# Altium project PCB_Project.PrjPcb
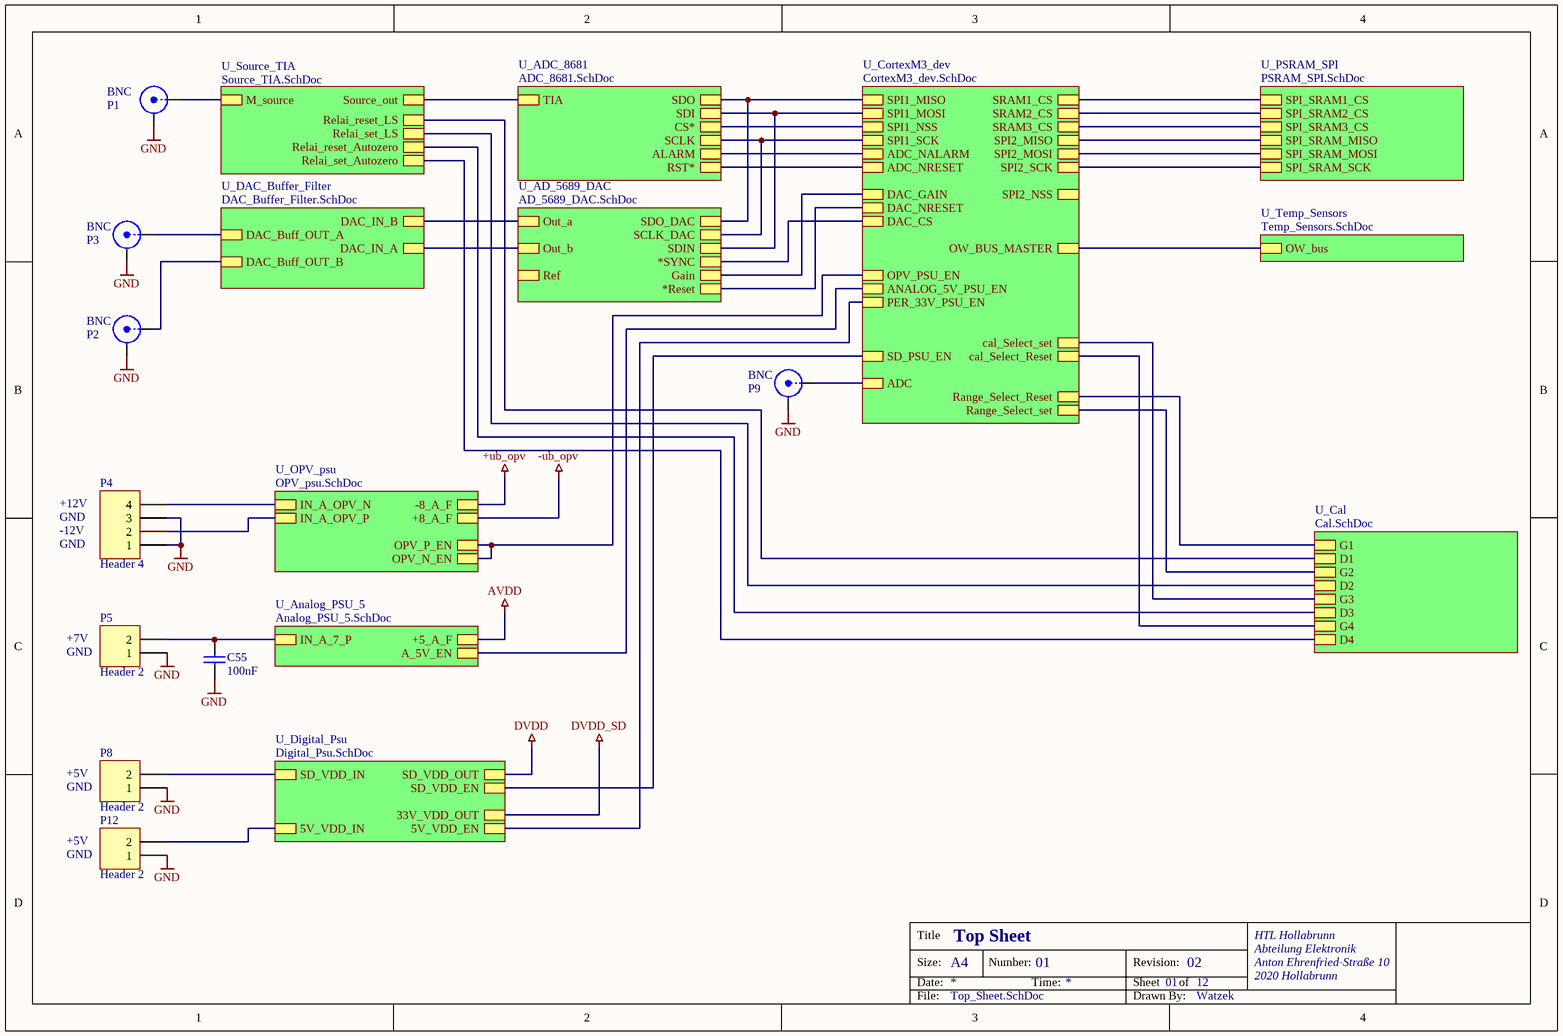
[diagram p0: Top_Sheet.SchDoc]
12 sheets, 142 parts. Net scope: hierarchical (ports join the sheet entries above them; power ports are global).
Board file: PCB1.PcbDoc
Sheets:
  Top_Sheet.SchDoc
    U_Source_TIA = Source_TIA.SchDoc
    U_PSRAM_SPI = PSRAM_SPI.SchDoc
    U_DAC_Buffer_Filter = DAC_Buffer_Filter.SchDoc
    U_ADC_8681 = ADC_8681.SchDoc
    U_AD_5689_DAC = AD_5689_DAC.SchDoc
    U_Temp_Sensors = Temp_Sensors.SchDoc
    U_Digital_Psu = Digital_Psu.SchDoc
    U_Analog_PSU_5 = Analog_PSU_5.SchDoc
    U_OPV_psu = OPV_psu.SchDoc
    U_CortexM3_dev = CortexM3_dev.SchDoc
    U_Cal = Cal.SchDoc

## Sheet Top_Sheet.SchDoc: Top Sheet
size A4; ApprovedBy: Watzek; CheckedBy: Watzek; Author: Watzek; DrawnBy: Watzek; Organization: HTL Hollabrunn; Address1: Abteilung Elektronik; Address2: Anton Ehrenfried-Straße 10; Address3: 2020 Hollabrunn; DocumentNumber: 01; Revision: 02; SheetNumber: 01; SheetTotal: 12; SPICEModelCacheIHPBHSPQ: <root> / <DocumentId>IHPBHSPQ</DocumentId> / <CacheFrame Number="0"> / <Model Name="cap" Kind="MDL"> / <Text>*Default semiconductor capacitor / .MODEL CAP C()</Text> / </Model> / </CacheFrame> / </root>

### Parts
C55  100nF  [C1206-KUE]
P1  BNC  [BNC_RA CON]
P2  BNC  [BNC_RA CON]
P3  BNC  [BNC_RA CON]
P4  Header 4  [HDR1X4]
P5  Header 2  [HDR1X2]
P8  Header 2  [HDR1X2]
P9  BNC  [BNC_RA CON]
P12  Header 2  [HDR1X2]

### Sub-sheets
U_AD_5689_DAC = AD_5689_DAC.SchDoc: Ref, Out_a, Out_b, SDIN, SDO_DAC, SCLK_DAC, *SYNC, Gain, *Reset
U_ADC_8681 = ADC_8681.SchDoc: SDI, CS*, SCLK, SDO, ALARM, RST*, TIA
U_Analog_PSU_5 = Analog_PSU_5.SchDoc: IN_A_7_P, +5_A_F, A_5V_EN
U_Cal = Cal.SchDoc: G1, G2, D1, D2, G3, D3, G4, D4
U_CortexM3_dev = CortexM3_dev.SchDoc: SPI1_NSS, SPI1_SCK, SPI1_MISO, SPI1_MOSI, SPI2_NSS, SPI2_MISO, SPI2_MOSI, SPI2_SCK, ADC_NALARM, ADC_NRESET, DAC_GAIN, DAC_NRESET, SRAM1_CS, SRAM2_CS, SRAM3_CS, DAC_CS, OW_BUS_MASTER, OPV_PSU_EN, ANALOG_5V_PSU_EN, PER_33V_PSU_EN, SD_PSU_EN, Range_Select_set, Range_Select_Reset, ADC, cal_Select_Reset, cal_Select_set
U_DAC_Buffer_Filter = DAC_Buffer_Filter.SchDoc: DAC_IN_B, DAC_Buff_OUT_B, DAC_IN_A, DAC_Buff_OUT_A
U_Digital_Psu = Digital_Psu.SchDoc: SD_VDD_IN, SD_VDD_OUT, SD_VDD_EN, 5V_VDD_IN, 33V_VDD_OUT, 5V_VDD_EN
U_OPV_psu = OPV_psu.SchDoc: IN_A_OPV_P, +8_A_F, IN_A_OPV_N, -8_A_F, OPV_P_EN, OPV_N_EN
U_PSRAM_SPI = PSRAM_SPI.SchDoc: SPI_SRAM_SCK, SPI_SRAM_MISO, SPI_SRAM1_CS, SPI_SRAM2_CS, SPI_SRAM3_CS, SPI_SRAM_MOSI
U_Source_TIA = Source_TIA.SchDoc: M_source, Source_out, Relai_set_LS, Relai_reset_LS, Relai_reset_Autozero, Relai_set_Autozero
U_Temp_Sensors = Temp_Sensors.SchDoc: OW_bus

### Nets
GND: C55.1 P1.2(Y) P2.2(Y) P3.2(Y) P4.1 P4.3 P5.1 P8.1 P9.2(Y) P12.1
M_source: P1.1(X) ; sheet U_Source_TIA/M_source
SPI1_CS_SRAM1: sheet U_PSRAM_SPI/SPI_SRAM1_CS, sheet U_CortexM3_dev/SRAM1_CS
SPI1_CS_SRAM2: sheet U_PSRAM_SPI/SPI_SRAM2_CS, sheet U_CortexM3_dev/SRAM2_CS
SPI1_CS_SRAM3: sheet U_PSRAM_SPI/SPI_SRAM3_CS, sheet U_CortexM3_dev/SRAM3_CS
SPI1_MISO: sheet U_ADC_8681/SDO, sheet U_AD_5689_DAC/SDO_DAC, sheet U_CortexM3_dev/SPI1_MISO
SPI1_MOSI: sheet U_ADC_8681/SDI, sheet U_AD_5689_DAC/SDIN, sheet U_CortexM3_dev/SPI1_MOSI
SPI1_SCK: sheet U_ADC_8681/SCLK, sheet U_AD_5689_DAC/SCLK_DAC, sheet U_CortexM3_dev/SPI1_SCK
SPI1_SRAM_MISO: sheet U_PSRAM_SPI/SPI_SRAM_MISO, sheet U_CortexM3_dev/SPI2_MISO
SPI1_SRAM_MOSI: sheet U_PSRAM_SPI/SPI_SRAM_MOSI, sheet U_CortexM3_dev/SPI2_MOSI
SPI1_SRAM_SCK: sheet U_PSRAM_SPI/SPI_SRAM_SCK, sheet U_CortexM3_dev/SPI2_SCK
NetC33_2: P8.2 ; sheet U_Digital_Psu/SD_VDD_IN
NetC36_2: P12.2 ; sheet U_Digital_Psu/5V_VDD_IN
NetC47_2: P4.2 ; sheet U_OPV_psu/IN_A_OPV_P
NetC49_2: P4.4 ; sheet U_OPV_psu/IN_A_OPV_N
NetC55_2: C55.2 P5.2 ; sheet U_Analog_PSU_5/IN_A_7_P
NetD5_2: sheet U_Source_TIA/Relai_set_LS, sheet U_Cal/D2
NetD6_2: sheet U_Source_TIA/Relai_reset_LS, sheet U_Cal/D1
NetD7_2: sheet U_Source_TIA/Relai_reset_Autozero, sheet U_Cal/D3
NetD8_2: sheet U_Source_TIA/Relai_set_Autozero, sheet U_Cal/D4
NetN3_7: sheet U_Source_TIA/Source_out, sheet U_ADC_8681/TIA
NetN3_11: sheet U_ADC_8681/CS*, sheet U_CortexM3_dev/SPI1_NSS
NetN3_14: sheet U_ADC_8681/ALARM, sheet U_CortexM3_dev/ADC_NALARM
NetN4_1: sheet U_AD_5689_DAC/*Reset, sheet U_CortexM3_dev/DAC_NRESET
NetN4_2: P9.1(X) ; sheet U_CortexM3_dev/ADC
NetN4_3: sheet U_AD_5689_DAC/*SYNC, sheet U_CortexM3_dev/DAC_CS
NetN4_4: sheet U_AD_5689_DAC/Gain, sheet U_CortexM3_dev/DAC_GAIN
NetN4_9: sheet U_CortexM3_dev/cal_Select_Reset, sheet U_Cal/G4
NetN4_10: sheet U_CortexM3_dev/cal_Select_set, sheet U_Cal/G3
NetN4_11: sheet U_CortexM3_dev/Range_Select_Reset, sheet U_Cal/G1
NetN4_12: sheet U_CortexM3_dev/Range_Select_set, sheet U_Cal/G2
NetN4_13: sheet U_OPV_psu/OPV_P_EN, sheet U_OPV_psu/OPV_N_EN, sheet U_CortexM3_dev/OPV_PSU_EN
NetN4_20: sheet U_Analog_PSU_5/A_5V_EN, sheet U_CortexM3_dev/ANALOG_5V_PSU_EN
NetN4_21: sheet U_Temp_Sensors/OW_bus, sheet U_CortexM3_dev/OW_BUS_MASTER
NetN4_27: sheet U_ADC_8681/RST*, sheet U_CortexM3_dev/ADC_NRESET
NetP2_1: P2.1(X) ; sheet U_DAC_Buffer_Filter/DAC_Buff_OUT_B
NetP3_1: P3.1(X) ; sheet U_DAC_Buffer_Filter/DAC_Buff_OUT_A
NetP7_10: sheet U_Digital_Psu/SD_VDD_EN, sheet U_CortexM3_dev/SD_PSU_EN
NetP7_12: sheet U_Digital_Psu/5V_VDD_EN, sheet U_CortexM3_dev/PER_33V_PSU_EN
NetR34_1: sheet U_DAC_Buffer_Filter/DAC_IN_B, sheet U_AD_5689_DAC/Out_a
NetR37_1: sheet U_DAC_Buffer_Filter/DAC_IN_A, sheet U_AD_5689_DAC/Out_b

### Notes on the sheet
- +12V
- GND
- -12V
- +7V
- +5V

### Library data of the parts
C55 = Capacitor: Manufacturer: Kemet; Bezeichnung: Kerko +-10% 63V
P1-P3 P9 = BNC: BNC Elbow Connector
P4 = Header 4: Header, 4-Pin
P5 P8 P12 = Header 2: Header, 2-Pin

## Sheet Source_TIA.SchDoc: TIA and damper
size A4; Author: Watzek; DrawnBy: Watzek; Organization: HTL Hollabrunn; Address1: Abteilung Elektronik; Address2: Anton Ehrenfried-Straße 10; Address3: 2020 Hollabrunn; DocumentNumber: 02; Revision: 02; SheetNumber: 02; SheetTotal: 12; SPICEModelCacheBSQSHVBX: <root> / <DocumentId>BSQSHVBX</DocumentId> / <CacheFrame Number="0"> / <Model Name="cap" Kind="MDL"> / <Text>*Default semiconductor capacitor / .MODEL CAP C()</Text> / </Model> / </CacheFrame> / </root>
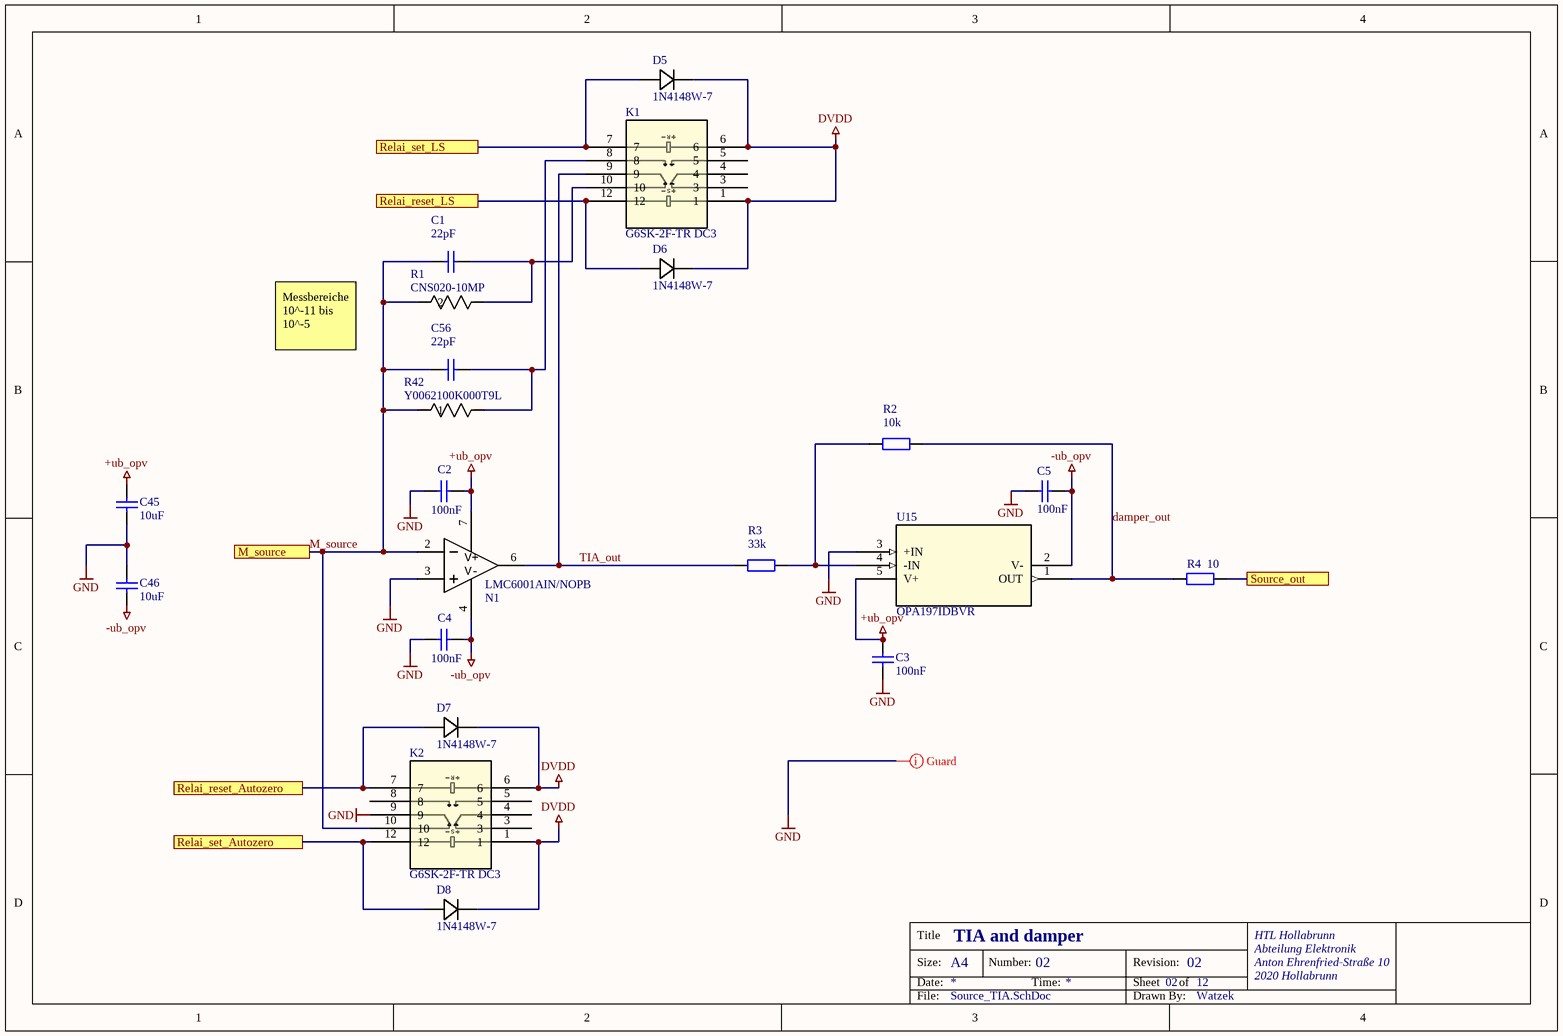
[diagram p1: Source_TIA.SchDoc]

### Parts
C1  22pF  [C1206-KUE]
C2  100nF  [C1206-KUE]
C3  100nF  [C1206-KUE]
C4  100nF  [C1206-KUE]
C5  100nF  [C1206-KUE]
C45  10uF  [C1206-KUE]
C46  10uF  [C1206-KUE]
C56  22pF  [C1206-KUE]
D5  1N4148W-7  [SOD123_DIO]
D6  1N4148W-7  [SOD123_DIO]
D7  1N4148W-7  [SOD123_DIO]
D8  1N4148W-7  [SOD123_DIO]
K1  G6SK-2F-TR DC3  [RELAY_G6SK-2F DC3_OMR]
K2  G6SK-2F-TR DC3  [RELAY_G6SK-2F DC3_OMR]
N1  LMC6001AIN/NOPB  [DIP8]
R1  CNS020-10MP  [RES_CNS020_VIS]
R2  10k  [C1206-KUE]
R3  33k  [C1206-KUE]
R4  10  [C1206-KUE]
R42  Y0062100K000T9L  [RES_S102K_7P62X2P67_VIS]
U15  OPA197IDBVR  [DBV5_TEX]

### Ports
M_source, Relai_reset_Autozero, Relai_reset_LS, Relai_set_Autozero, Relai_set_LS, Source_out

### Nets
+ub_opv: C2.2 C3.2 C45.2 N1.7(V+) U15.5(V+)  [project net neg_out]
-ub_opv: C4.2 C5.2 C46.1 N1.4(V-) U15.2(V-)  [project net pos_out]
DVDD: D5.1 D6.1 D7.1 D8.1 K1.1 K1.6 K2.1 K2.6
GND: C2.1 C3.1 C4.1 C5.1 C45.1 C46.2 K2.9 N1.3(IN+) U15.3(+IN)
damper_out: R2.1 R4.2 U15.1(OUT)
M_source: C1.1 C56.1 K2.10 N1.2(IN-) R1.2 R42.1 ; port M_source
TIA_out: K1.9 N1.6(OUT) R3.2
NetC1_2: C1.2 K1.10 R1.1
NetC56_2: C56.2 K1.8 R42.2
NetD5_2: D5.2 K1.7 ; port Relai_set_LS
NetD6_2: D6.2 K1.12 ; port Relai_reset_LS
NetD7_2: D7.2 K2.7 ; port Relai_reset_Autozero
NetD8_2: D8.2 K2.12 ; port Relai_set_Autozero
NetN3_7: R4.1 ; port Source_out
NetR2_2: R2.2 R3.1 U15.4(-IN)

Not connected (* = marked no-connect by the designer): K1 3 4 5; K2 3 4 5 8

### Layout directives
mark named Guard: GND

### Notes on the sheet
- Messbereiche 10^-11 bis 10^-5

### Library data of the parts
C1-C5 C45 C46 C56 = Capacitor: as C55 on sheet Top_Sheet
D5-D8 = 1N4148W-7: Description; Manufacturer_Name: Diodes Inc
K1 K2 = G6SK-2F-TR DC3: Description; Manufacturer_Name: Omron
N1 = LMC6001AINNOPB: Ultra-Low Input Current Amplifier 8-PDIP -40 to 85; Manufacturer_Name: Texas Instruments; Manufacturer: NationalSemiconductor; Characteristics: LMC6001AINUltra-LowInputBiasCurrentOpAmp; CompType: OpAmpIC; TaMin_C: -400; TaMax_C: 850; ComponentLink1DescBC: LMC6001Datasheet; ComponentLink2DescA4: LMC6001WebPage; ComponentLink3DescAC: N08EPackageWebPage
R1 = CNS020-10KP: CNS 020 10K 0,02% e2; Manufacturer_Name: Vishay
R2-R4 = ResistorSMD: Resistor SMD; Manufacturer: AVX; Bezeichnung: SMD Wid. 1/8W 2%
R42 = Y0062100K000T9L: No Description Available; Manufacturer_Name: Vishay
U15 = OPA197IDBVR: Single, 36-V, precision, rail-to-rail input output, low offset voltage op amp 5-SOT-23 -40 to 125; Manufacturer_Name: Texas Instruments

## Sheet PSRAM_SPI.SchDoc: SRAM
size A4; DrawnBy: Michael Watzek; Organization: HTL Hollabrunn; Address1: Abteilung Elektronik; Address2: Anton Ehrenfried-Straße 10; Address3: 2020 Hollabrunn; DocumentNumber: 08; Revision: 02; SheetNumber: 08; SheetTotal: 12; SPICEModelCacheKLVIFSCJ: <root> / <DocumentId>KLVIFSCJ</DocumentId> / <CacheFrame Number="0"> / <Model Name="cap" Kind="MDL"> / <Text>*Default semiconductor capacitor / .MODEL CAP C()</Text> / </Model> / </CacheFrame> / </root>
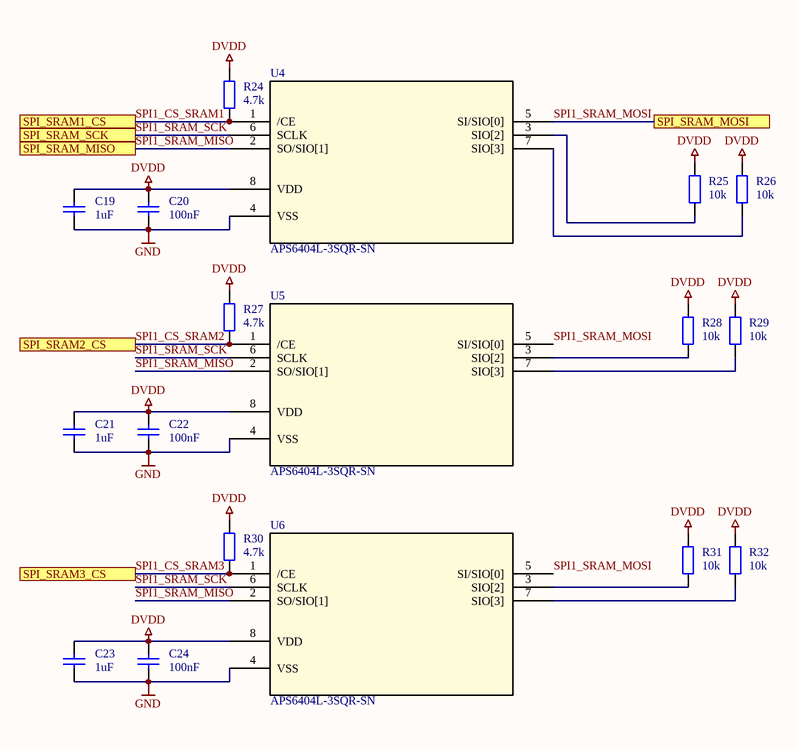
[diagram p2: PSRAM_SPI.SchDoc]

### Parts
C19  1uF  [C1206-KUE]
C20  100nF  [C1206-KUE]
C21  1uF  [C1206-KUE]
C22  100nF  [C1206-KUE]
C23  1uF  [C1206-KUE]
C24  100nF  [C1206-KUE]
R24  4.7k  [C1206-KUE]
R25  10k  [C1206-KUE]
R26  10k  [C1206-KUE]
R27  4.7k  [C1206-KUE]
R28  10k  [C1206-KUE]
R29  10k  [C1206-KUE]
R30  4.7k  [C1206-KUE]
R31  10k  [C1206-KUE]
R32  10k  [C1206-KUE]
U4  APS6404L-3SQR-SN  [APS6404L-3SQR-SN_APY]
U5  APS6404L-3SQR-SN  [APS6404L-3SQR-SN_APY]
U6  APS6404L-3SQR-SN  [APS6404L-3SQR-SN_APY]

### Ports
SPI_SRAM1_CS, SPI_SRAM2_CS, SPI_SRAM3_CS, SPI_SRAM_MISO, SPI_SRAM_MOSI, SPI_SRAM_SCK

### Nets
DVDD: C19.2 C20.2 C21.2 C22.2 C23.2 C24.2 R24.1 R25.1 R26.1 R27.1 R28.1 R29.1 R30.1 R31.1 R32.1 U4.8(VDD) U5.8(VDD) U6.8(VDD)
GND: C19.1 C20.1 C21.1 C22.1 C23.1 C24.1 U4.4(VSS) U5.4(VSS) U6.4(VSS)
SPI1_CS_SRAM1: R24.2 U4.1(/CE) ; port SPI_SRAM1_CS
SPI1_CS_SRAM2: R27.2 U5.1(/CE) ; port SPI_SRAM2_CS
SPI1_CS_SRAM3: R30.2 U6.1(/CE) ; port SPI_SRAM3_CS
SPI1_SRAM_MISO: U4.2(SO/SIO[1]) U5.2(SO/SIO[1]) U6.2(SO/SIO[1]) ; port SPI_SRAM_MISO
SPI1_SRAM_MOSI: U4.5(SI/SIO[0]) U5.5(SI/SIO[0]) U6.5(SI/SIO[0]) ; port SPI_SRAM_MOSI
SPI1_SRAM_SCK: U4.6(SCLK) U5.6(SCLK) U6.6(SCLK) ; port SPI_SRAM_SCK
NetR25_2: R25.2 U4.3(SIO[2])
NetR26_2: R26.2 U4.7(SIO[3])
NetR28_2: R28.2 U5.3(SIO[2])
NetR29_2: R29.2 U5.7(SIO[3])
NetR31_2: R31.2 U6.3(SIO[2])
NetR32_2: R32.2 U6.7(SIO[3])

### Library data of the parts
C19-C24 = Capacitor: as C55 on sheet Top_Sheet
R24-R32 = ResistorSMD: as R2 on sheet Source_TIA
U4-U6 = APS6404L-3SQR-SN: Description; Manufacturer_Name: AP Memory

## Sheet DAC_Buffer_Filter.SchDoc: DAC Buffer
size A4; DrawnBy: Michael Watzek; Organization: HTL Hollabrunn; Address1: Abteilung Elektronik; Address2: Anton Ehrenfried-Straße 10; Address3: 2020 Hollabrunn; DocumentNumber: 09; Revision: 01; SheetNumber: 09; SheetTotal: 12; SPICEModelCacheDRLOHMHD: <root> / <DocumentId>DRLOHMHD</DocumentId> / <CacheFrame Number="0"> / <Model Name="cap" Kind="MDL"> / <Text>*Default semiconductor capacitor / .MODEL CAP C()</Text> / </Model> / </CacheFrame> / </root>
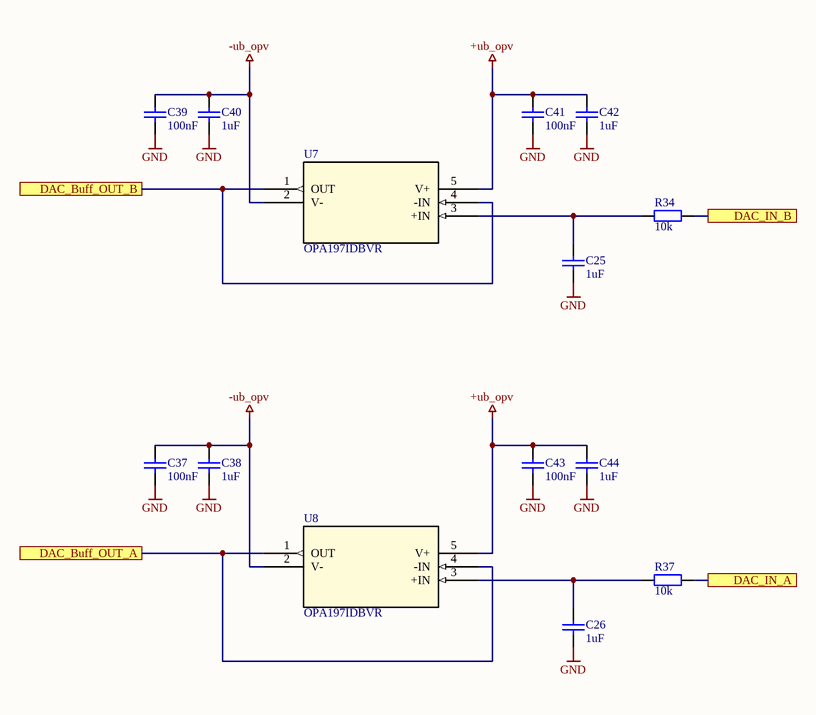
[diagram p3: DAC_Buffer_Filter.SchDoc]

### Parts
C25  1uF  [C1206-KUE]
C26  1uF  [C1206-KUE]
C37  100nF  [C1206-KUE]
C38  1uF  [C1206-KUE]
C39  100nF  [C1206-KUE]
C40  1uF  [C1206-KUE]
C41  100nF  [C1206-KUE]
C42  1uF  [C1206-KUE]
C43  100nF  [C1206-KUE]
C44  1uF  [C1206-KUE]
R34  10k  [C1206-KUE]
R37  10k  [C1206-KUE]
U7  OPA197IDBVR  [DBV5_TEX]
U8  OPA197IDBVR  [DBV5_TEX]

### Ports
DAC_Buff_OUT_A, DAC_Buff_OUT_B, DAC_IN_A, DAC_IN_B

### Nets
+ub_opv: C41.2 C42.2 C43.2 C44.2 U7.5(V+) U8.5(V+)  [project net neg_out]
-ub_opv: C37.2 C38.2 C39.2 C40.2 U7.2(V-) U8.2(V-)  [project net pos_out]
GND: C25.1 C26.1 C37.1 C38.1 C39.1 C40.1 C41.1 C42.1 C43.1 C44.1
NetC25_2: C25.2 R34.2 U7.3(+IN)
NetC26_2: C26.2 R37.2 U8.3(+IN)
NetP2_1: U7.1(OUT) U7.4(-IN) ; port DAC_Buff_OUT_B
NetP3_1: U8.1(OUT) U8.4(-IN) ; port DAC_Buff_OUT_A
NetR34_1: R34.1 ; port DAC_IN_B
NetR37_1: R37.1 ; port DAC_IN_A

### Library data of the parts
C25 C26 C37-C44 = Capacitor: as C55 on sheet Top_Sheet
R34 R37 = ResistorSMD: as R2 on sheet Source_TIA
U7 U8 = OPA197IDBVR: as U15 on sheet Source_TIA

## Sheet ADC_8681.SchDoc: source ADC
size A4; Author: Watzek; DrawnBy: Watzek; Organization: HTL Hollabrunn; Address1: Abteilung Elektronik; Address2: Anton Ehrenfried-Straße 10; Address3: 2020 Hollabrunn; DocumentNumber: 04; Revision: 01; SheetNumber: 04; SheetTotal: 12; SPICEModelCacheSWPEVHXS: <root> / <DocumentId>SWPEVHXS</DocumentId> / <CacheFrame Number="0"> / <Model Name="cap" Kind="MDL"> / <Text>*Default semiconductor capacitor / .MODEL CAP C()</Text> / </Model> / </CacheFrame> / </root>
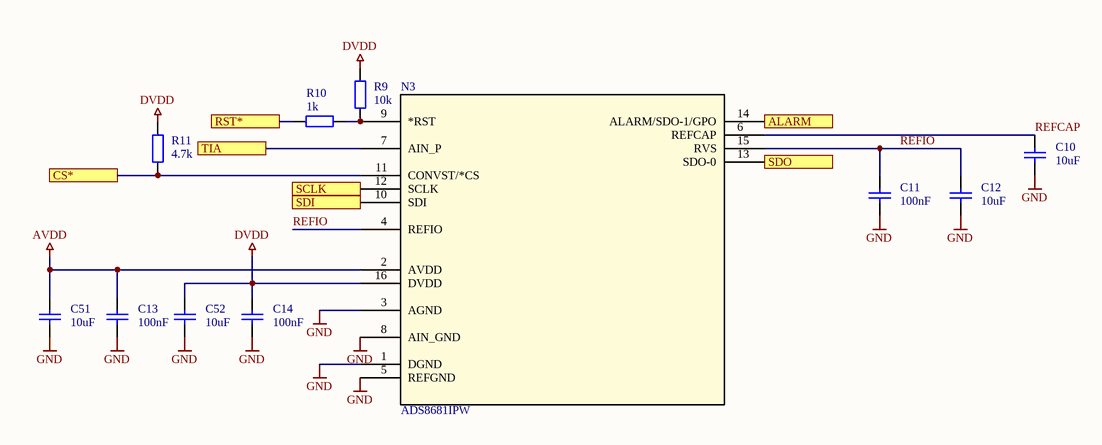
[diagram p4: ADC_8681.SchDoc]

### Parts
C10  10uF  [C1206-KUE]
C11  100nF  [C1206-KUE]
C12  10uF  [C1206-KUE]
C13  100nF  [C1206-KUE]
C14  100nF  [C1206-KUE]
C51  10uF  [C1206-KUE]
C52  10uF  [C1206-KUE]
N3  ADS8681IPW  [PW16_TEX]
R9  10k  [C1206-KUE]
R10  1k  [C1206-KUE]
R11  4.7k  [C1206-KUE]

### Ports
ALARM, CS*, RST*, SCLK, SDI, SDO, TIA

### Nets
AVDD: C13.2 C51.2 N3.2(AVDD)
DVDD: C14.2 C52.2 N3.16(DVDD) R9.1 R11.1
GND: C10.1 C11.1 C12.1 C13.1 C14.1 C51.1 C52.1 N3.1(DGND) N3.3(AGND) N3.5(REFGND) N3.8(AIN_GND)
REFCAP: C10.2 N3.6(REFCAP)
REFIO: C11.2 C12.2 N3.4(REFIO) N3.15(RVS)
SPI1_MISO: N3.13(SDO-0) ; port SDO
SPI1_MOSI: N3.10(SDI) ; port SDI
SPI1_SCK: N3.12(SCLK) ; port SCLK
NetN3_7: N3.7(AIN_P) ; port TIA
NetN3_9: N3.9(*RST) R9.2 R10.2
NetN3_11: N3.11(CONVST/*CS) R11.2 ; port CS*
NetN3_14: N3.14(ALARM/SDO-1/GPO) ; port ALARM
NetN4_27: R10.1 ; port RST*

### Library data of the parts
C10-C14 C51 C52 = Capacitor: as C55 on sheet Top_Sheet
N3 = ADS8681IPW: 16-bit, 1MSPS 1-ch SAR ADC with programmable (Â±12V, Â±10V, Â±6V, Â±5V, Â±2.5V) input ranges on 5V supply 16-TSSOP -40 to 125; Manufacturer_Name: Texas Instruments
R9-R11 = ResistorSMD: as R2 on sheet Source_TIA

## Sheet AD_5689_DAC.SchDoc: DAC for Gate / Drain
size A4; Author: Watzek; DrawnBy: Watzek; Organization: HTL Hollabrunn; Address1: Abteilung Elektronik; Address2: Anton Ehrenfried-Straße 10; Address3: 2020 Hollabrunn; DocumentNumber: 05; Revision: 01; SheetNumber: 05; SheetTotal: 12; SPICEModelCacheXXRROZRR: <root> / <DocumentId>XXRROZRR</DocumentId> / <CacheFrame Number="0"> / <Model Name="cap" Kind="MDL"> / <Text>*Default semiconductor capacitor / .MODEL CAP C()</Text> / </Model> / </CacheFrame> / </root>
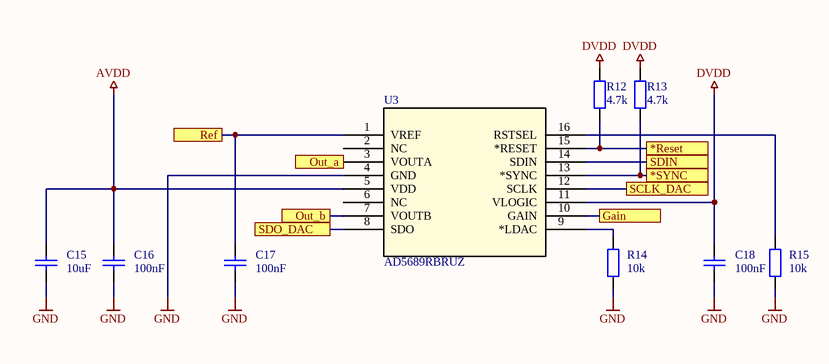
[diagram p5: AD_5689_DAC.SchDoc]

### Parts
C15  10uF  [C1206-KUE]
C16  100nF  [C1206-KUE]
C17  100nF  [C1206-KUE]
C18  100nF  [C1206-KUE]
R12  4.7k  [C1206-KUE]
R13  4.7k  [C1206-KUE]
R14  10k  [C1206-KUE]
R15  10k  [C1206-KUE]
U3  AD5689RBRUZ  [RU_16_ADI]

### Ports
*Reset, *SYNC, Gain, Out_a, Out_b, Ref, SCLK_DAC, SDIN, SDO_DAC

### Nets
AVDD: C15.2 C16.2 U3.5(VDD)
DVDD: C18.2 R12.1 R13.1 U3.11(VLOGIC)
GND: C15.1 C16.1 C17.1 C18.1 R14.2 R15.2 U3.4(GND)
SPI1_MISO: U3.8(SDO) ; port SDO_DAC
SPI1_MOSI: U3.14(SDIN) ; port SDIN
SPI1_SCK: U3.12(SCLK) ; port SCLK_DAC
NetC17_2: C17.2 U3.1(VREF) ; port Ref
NetN4_1: R12.2 U3.15(*RESET) ; port *Reset
NetN4_3: R13.2 U3.13(*SYNC) ; port *SYNC
NetN4_4: U3.10(GAIN) ; port Gain
NetR14_1: R14.1 U3.9(*LDAC)
NetR15_1: R15.1 U3.16(RSTSEL)
NetR34_1: U3.3(VOUTA) ; port Out_a
NetR37_1: U3.7(VOUTB) ; port Out_b

Not connected (* = marked no-connect by the designer): U3 2(NC) 6(NC)

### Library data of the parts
C15-C18 = Capacitor: as C55 on sheet Top_Sheet
R12-R15 = ResistorSMD: as R2 on sheet Source_TIA
U3 = AD5689RBRUZ: Dual, 16-Bit nanoDAC+ with 2 ppm/Â°C Reference, SPI Interface; Manufacturer_Name: Analog Devices Inc

## Sheet Temp_Sensors.SchDoc: One Wire Devices
size A4; DrawnBy: Michael Watzek; Organization: HTL Hollabrunn; Address1: Abteilung Elektronik; Address2: Anton Ehrenfried-Straße 10; Address3: 2020 Hollabrunn; DocumentNumber: 10; Revision: 01; SheetNumber: 10; SheetTotal: 12
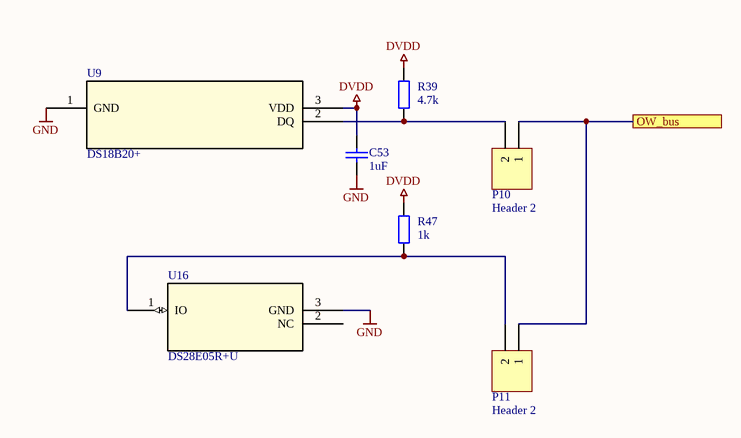
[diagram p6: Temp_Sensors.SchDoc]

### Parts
C53  1uF  [C1206-KUE]
P10  Header 2  [HDR1X2]
P11  Header 2  [HDR1X2]
R39  4.7k  [C1206-KUE]
R47  1k  [C1206-KUE]
U9  DS18B20+  [21-0248A_Q3-1_MXM]
U16  DS28E05R+U  [21-0051H_MXM]

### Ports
OW_bus

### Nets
DVDD: C53.2 R39.1 R47.1 U9.3(VDD)
GND: C53.1 U9.1(GND) U16.3(GND)
NetN4_21: P10.1 P11.1 ; port OW_bus
NetP10_2: P10.2 R39.2 U9.2(DQ)
NetP11_2: P11.2 R47.2 U16.1(IO)

Not connected (* = marked no-connect by the designer): U16 2(NC)

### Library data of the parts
C53 = Capacitor: as C55 on sheet Top_Sheet
P10 P11 = Header 2: Header, 2-Pin
R39 R47 = ResistorSMD: as R2 on sheet Source_TIA
U9 = DS18B20+: Programmable Resolution 1-Wire Digital Thermometer; Manufacturer_Name: Analog Devices Inc
U16 = DS28E05R+U: 1-Wire EEPROM; Manufacturer_Name: Analog Devices Inc

## Sheet Digital_Psu.SchDoc: Digital PSU
size A4; DrawnBy: Michael Watzek; Organization: HTL Hollabrunn; Address1: Abteilung Elektronik; Address2: Anton Ehrenfried-Straße 10; Address3: 2020 Hollabrunn; DocumentNumber: 07; Revision: 02; SheetNumber: 07; SheetTotal: 12; SPICEModelCacheAWIPVUZH: <root> / <DocumentId>AWIPVUZH</DocumentId> / <CacheFrame Number="0"> / <Model Name="cap" Kind="MDL"> / <Text>*Default semiconductor capacitor / .MODEL CAP C()</Text> / </Model> / </CacheFrame> / </root>
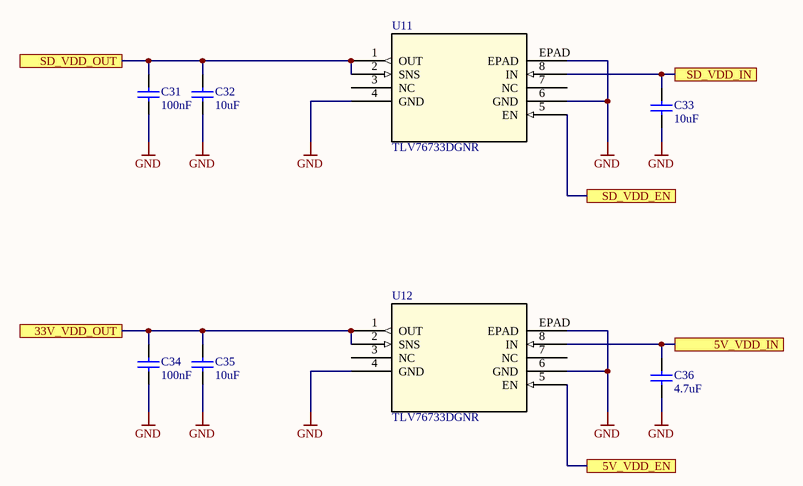
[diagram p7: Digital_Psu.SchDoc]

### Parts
C31  100nF  [C1206-KUE]
C32  10uF  [C1206-KUE]
C33  10uF  [C1206-KUE]
C34  100nF  [C1206-KUE]
C35  10uF  [C1206-KUE]
C36  4.7uF  [C1206-KUE]
U11  TLV76733DGNR  [VSSOP8_DGN_TEX]
U12  TLV76733DGNR  [VSSOP8_DGN_TEX]

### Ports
5V_VDD_EN, 5V_VDD_IN, 33V_VDD_OUT, SD_VDD_EN, SD_VDD_IN, SD_VDD_OUT

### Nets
DVDD: C31.2 C32.2 U11.1(OUT) U11.2(SNS) ; port SD_VDD_OUT
DVDD_SD: C34.2 C35.2 U12.1(OUT) U12.2(SNS) ; port 33V_VDD_OUT
GND: C31.1 C32.1 C33.1 C34.1 C35.1 C36.1 U11.4(GND) U11.6(GND) U11.EPAD U12.4(GND) U12.6(GND) U12.EPAD
NetC33_2: C33.2 U11.8(IN) ; port SD_VDD_IN
NetC36_2: C36.2 U12.8(IN) ; port 5V_VDD_IN
NetP7_10: U11.5(EN) ; port SD_VDD_EN
NetP7_12: U12.5(EN) ; port 5V_VDD_EN

Not connected (* = marked no-connect by the designer): U11 3(NC) 7(NC); U12 3(NC) 7(NC)

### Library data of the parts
C31-C36 = Capacitor: as C55 on sheet Top_Sheet
U11 U12 = TLV76733DGNR: Adjustable- and fixed-output, 1-A, 16-V, positive-voltage low-dropout (LDO) linear regulator 8-HVSSOP -40 to 125; Manufacturer_Name: Texas Instruments

## Sheet Analog_PSU_5.SchDoc: Analog PSU
size A4; DrawnBy: Michael Watzek; Organization: HTL Hollabrunn; Address1: Abteilung Elektronik; Address2: Anton Ehrenfried-Straße 10; Address3: 2020 Hollabrunn; DocumentNumber: 11; Revision: 02; SheetNumber: 11; SheetTotal: 12; SPICEModelCacheRYPOANGS: <root> / <DocumentId>RYPOANGS</DocumentId> / <CacheFrame Number="0"> / <Model Name="cap" Kind="MDL"> / <Text>*Default semiconductor capacitor / .MODEL CAP C()</Text> / </Model> / </CacheFrame> / </root>
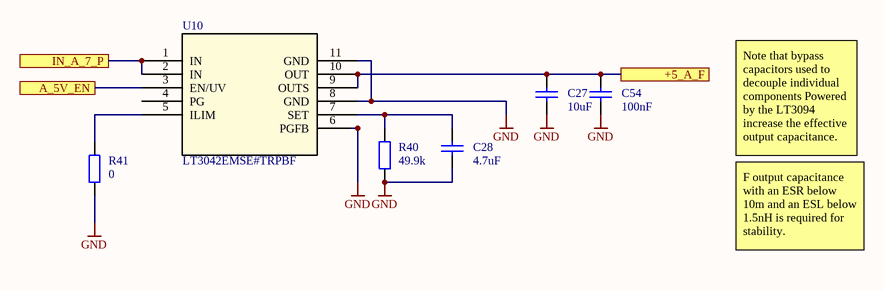
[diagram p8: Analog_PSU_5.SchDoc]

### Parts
C27  10uF  [C1206-KUE]
C28  4.7uF  [C1206-KUE]
C54  100nF  [C1206-KUE]
R40  49.9k  [C1206-KUE]
R41  0  [C1206-KUE]
U10  LT3042EMSE#TRPBF  [05-08-1664_ADI]

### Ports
+5_A_F, A_5V_EN, IN_A_7_P

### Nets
AVDD: C27.2 C54.2 U10.9(OUTS) U10.10(OUT) ; port +5_A_F
GND: C27.1 C28.1 C54.1 R40.2 R41.2 U10.6(PGFB) U10.8(GND) U10.11(GND)
NetC28_2: C28.2 R40.1 U10.7(SET)
NetC55_2: U10.1(IN) U10.2(IN) ; port IN_A_7_P
NetN4_20: U10.3(EN/UV) ; port A_5V_EN
NetR41_1: R41.1 U10.5(ILIM)

Not connected (* = marked no-connect by the designer): U10 4(PG)

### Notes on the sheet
- Note that bypass capacitors used to decouple individual components Powered by the LT3094 increase the effective output capacitance.
- F output capacitance with an ESR below 10m and an ESL below 1.5nH is required for stability.

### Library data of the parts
C27 C28 C54 = Capacitor: as C55 on sheet Top_Sheet
R40 R41 = ResistorSMD: as R2 on sheet Source_TIA
U10 = LT3042EMSETRPBF: 20V, 200mA, Ultralow Noise, Ultrahigh PSRR RF Linear Regulator; Manufacturer_Name: Analog Devices Inc

## Sheet OPV_psu.SchDoc: OPV Power supply
size A4; DrawnBy: Watzek; Organization: HTL Hollabrunn; Address1: Abteilung Elektronik; Address2: Anton Ehrenfried-Straße 10; Address3: 2020 Hollabrunn; DocumentNumber: 03; Revision: 01; SheetNumber: 03; SheetTotal: 12; SPICEModelCacheVBIYTPZR: <root> / <DocumentId>VBIYTPZR</DocumentId> / <CacheFrame Number="0"> / <Model Name="cap" Kind="MDL"> / <Text>*Default semiconductor capacitor / .MODEL CAP C()</Text> / </Model> / </CacheFrame> / </root>
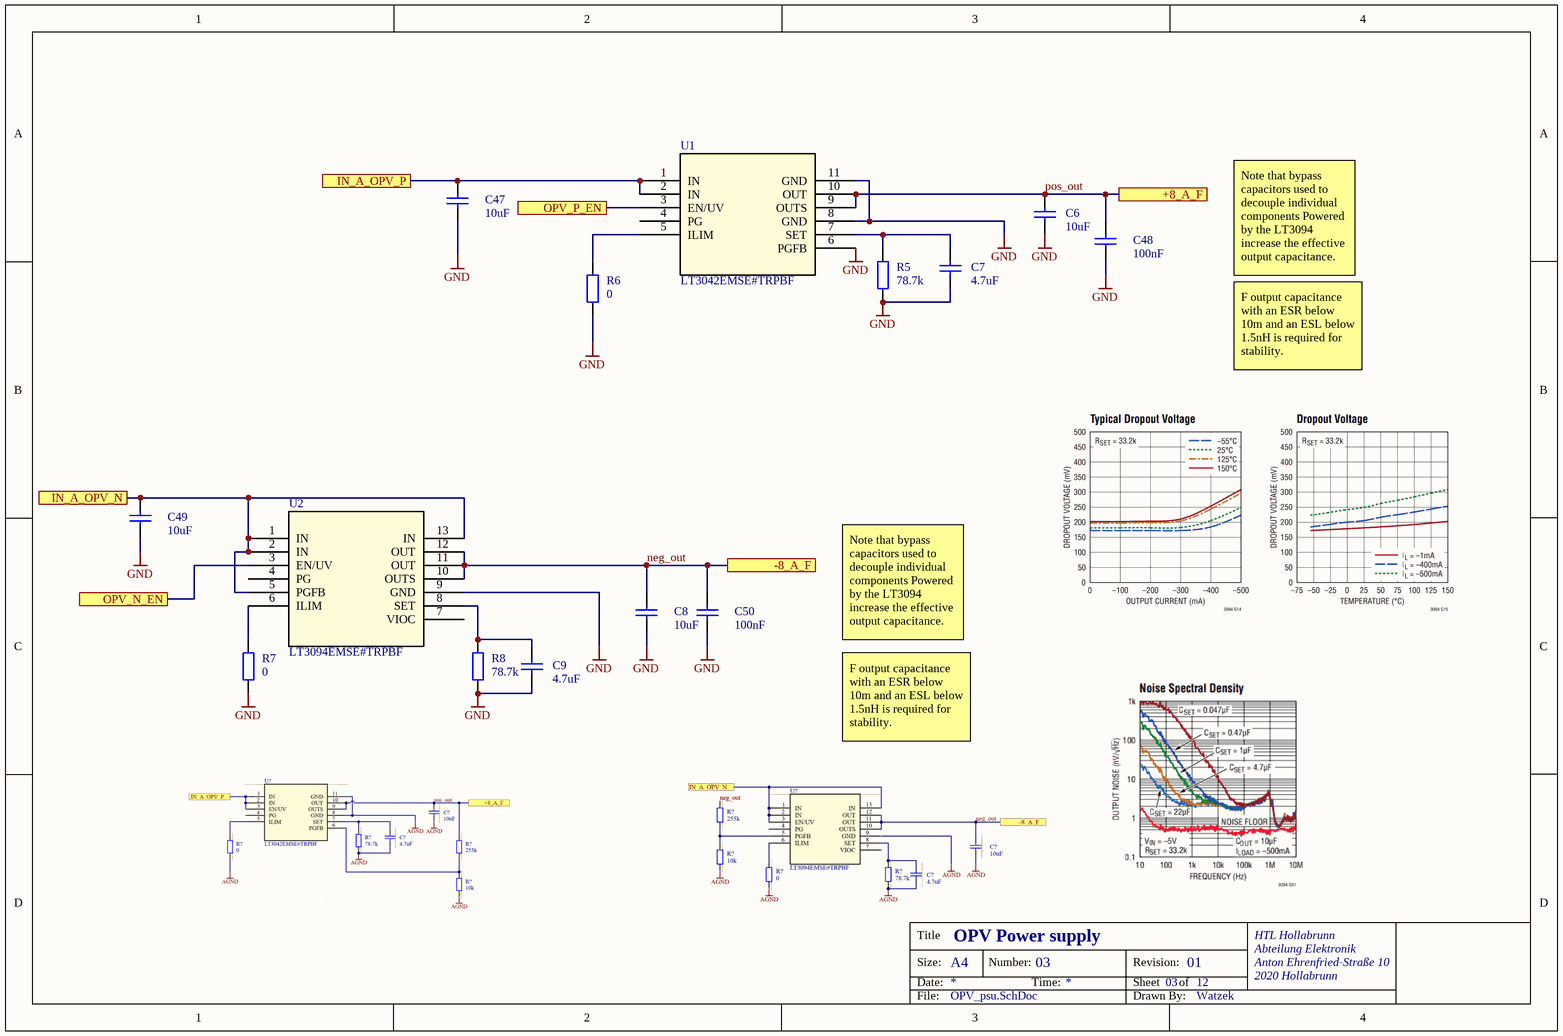
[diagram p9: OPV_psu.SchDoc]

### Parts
C6  10uF  [C1206-KUE]
C7  4.7uF  [C1206-KUE]
C8  10uF  [C1206-KUE]
C9  4.7uF  [C1206-KUE]
C47  10uF  [C1206-KUE]
C48  100nF  [C1206-KUE]
C49  10uF  [C1206-KUE]
C50  100nF  [C1206-KUE]
R5  78.7k  [C1206-KUE]
R6  0  [C1206-KUE]
R7  0  [C1206-KUE]
R8  78.7k  [C1206-KUE]
U1  LT3042EMSE#TRPBF  [05-08-1664_ADI]
U2  LT3094EMSE#TRPBF  [MSE_05-08-1666_ADI]

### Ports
+8_A_F, -8_A_F, IN_A_OPV_N, IN_A_OPV_P, OPV_N_EN, OPV_P_EN

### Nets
GND: C6.1 C7.1 C8.1 C9.1 C47.1 C48.1 C49.1 C50.1 R5.2 R6.2 R7.2 R8.2 U1.6(PGFB) U1.8(GND) U1.11(GND) U2.9(GND)
neg_out: C8.2 C50.2 U2.10(OUTS) U2.11(OUT) U2.12(OUT) ; port -8_A_F
pos_out: C6.2 C48.2 U1.9(OUTS) U1.10(OUT) ; port +8_A_F
NetC7_2: C7.2 R5.1 U1.7(SET)
NetC9_2: C9.2 R8.1 U2.8(SET)
NetC47_2: C47.2 U1.1(IN) U1.2(IN) ; port IN_A_OPV_P
NetC49_2: C49.2 U2.1(IN) U2.2(IN) U2.5(PGFB) U2.13(IN) ; port IN_A_OPV_N
NetN4_13: U1.3(EN/UV) U2.3(EN/UV) ; port OPV_P_EN, port OPV_N_EN
NetR6_1: R6.1 U1.5(ILIM)
NetR7_1: R7.1 U2.6(ILIM)

Not connected (* = marked no-connect by the designer): U1 4(PG); U2 4(PG) 7(VIOC)

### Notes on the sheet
- Note that bypass capacitors used to decouple individual components Powered by the LT3094 increase the effective output capacitance.
- F output capacitance with an ESR below 10m and an ESL below 1.5nH is required for stability.

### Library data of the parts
C6-C9 C47-C50 = Capacitor: as C55 on sheet Top_Sheet
R5-R8 = ResistorSMD: as R2 on sheet Source_TIA
U1 = LT3042EMSETRPBF: as U10 on sheet Analog_PSU_5
U2 = LT3094EMSETRPBF: âˆ’20V, 500mA, Ultralow Noise, Ultrahigh PSRR Negative Linear Regulator; Manufacturer_Name: Analog Devices Inc

## Sheet CortexM3_dev.SchDoc: Cortex M3 Dev and Memory
size A4; DrawnBy: Watzek; Organization: HTL Hollabrunn; Address1: Abteilung Elektronik; Address2: Anton Ehrenfried-Straße 10; Address3: 2020 Hollabrunn; DocumentNumber: 06; Revision: 01; SheetNumber: 06; SheetTotal: 12; SPICEModelCacheGTJPSRCJ: <root> / <DocumentId>GTJPSRCJ</DocumentId> / <CacheFrame Number="0"> / <Model Name="led0" Kind="MDL"> / <Text>*Typ INFRARED GaAs LED: Vf=1.2V Vr=5V If=40mA trr=3uS / *LED Pinout: 1=A, 2=K / .MODEL LED0 D (IS=93.5P RS=84M N=2.63 BV=5 IBV=10U / + CJO=2.97P VJ=.75 M=.333 TT=4.32U)</Text> / </Model> / <Model Name="cap" Kind="MDL"> / <Text>*Default semiconductor capacitor / .MODEL CAP C()</Text> / </Model> / </CacheFrame> / </root>
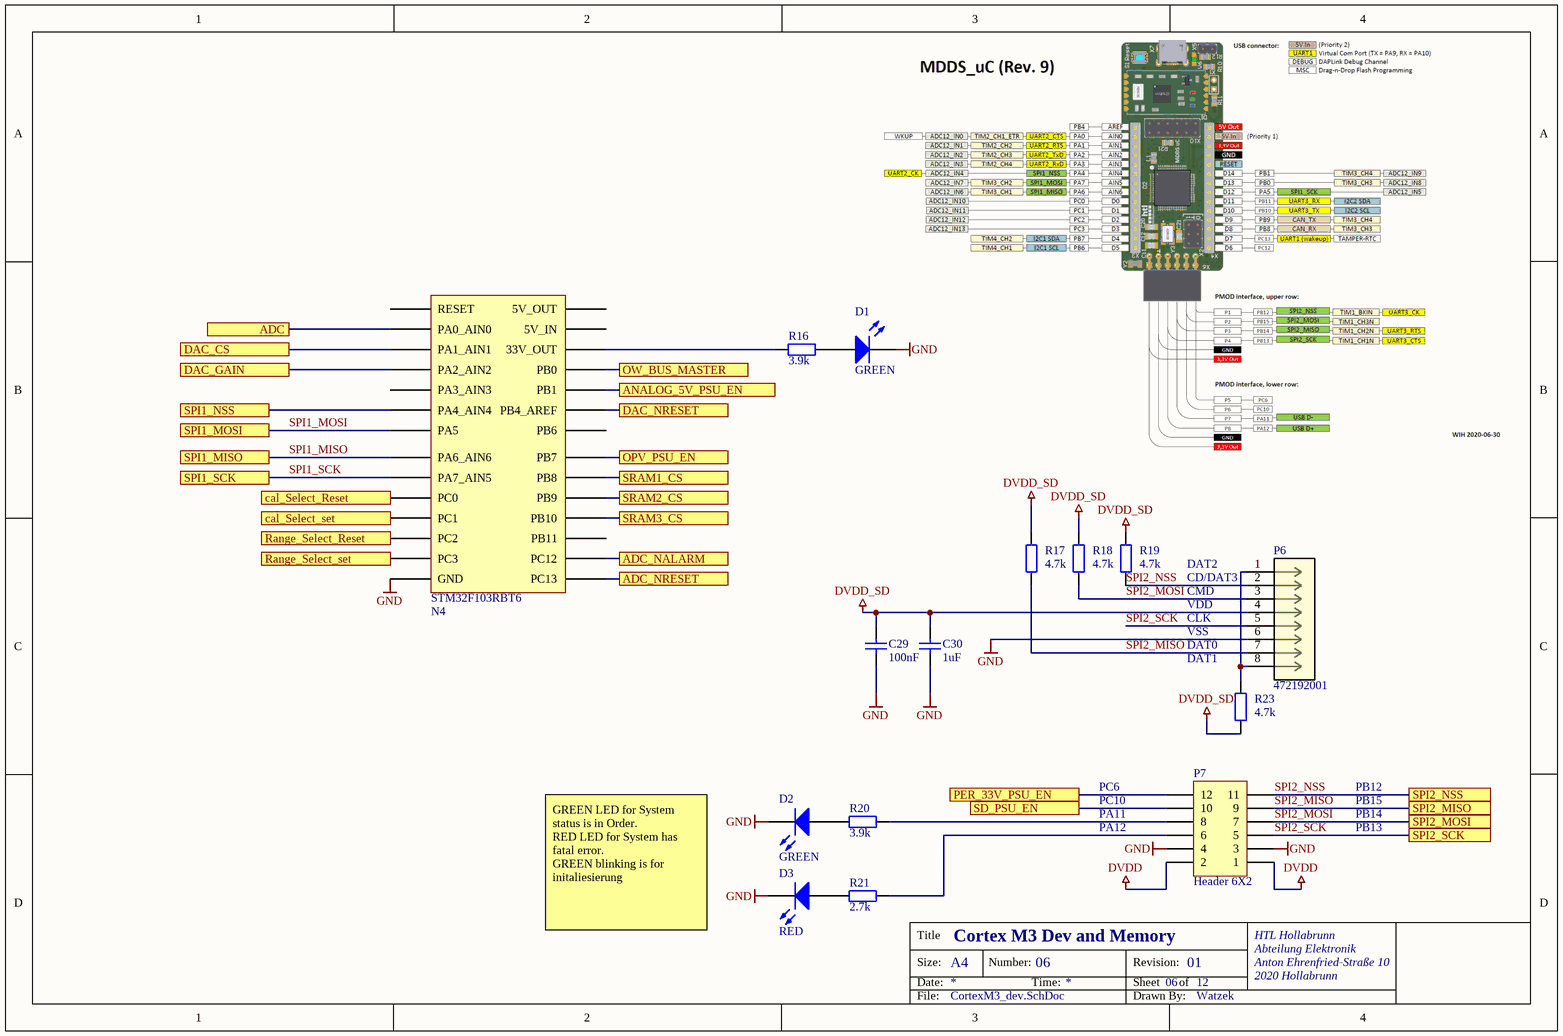
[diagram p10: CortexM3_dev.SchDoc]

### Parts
C29  100nF  [C1206-KUE]
C30  1uF  [C1206-KUE]
D1  GREEN  [6-0805_N-KUE]
D2  GREEN  [6-0805_N-KUE]
D3  RED  [6-0805_N-KUE]
N4  STM32F103  [DIP28]  (value not drawn)
P6  472192001  [CONN_47219-2001_MOL]
P7  Header 6X2  [HDR2X6]
R16  3.9k  [C1206-KUE]
R17  4.7k  [C1206-KUE]
R18  4.7k  [C1206-KUE]
R19  4.7k  [C1206-KUE]
R20  3.9k  [C1206-KUE]
R21  2.7k  [C1206-KUE]
R23  4.7k  [C1206-KUE]

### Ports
ADC, ADC_NALARM, ADC_NRESET, ANALOG_5V_PSU_EN, cal_Select_Reset, cal_Select_set, DAC_CS, DAC_GAIN, DAC_NRESET, OPV_PSU_EN, OW_BUS_MASTER, PER_33V_PSU_EN, Range_Select_Reset, Range_Select_set, SD_PSU_EN, SPI1_MISO, SPI1_MOSI, SPI1_NSS, SPI1_SCK, SPI2_MISO, SPI2_MOSI, SPI2_NSS, SPI2_SCK, SRAM1_CS, SRAM2_CS, SRAM3_CS

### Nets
DVDD: P7.1 P7.2
DVDD_SD: C29.2 C30.2 P6.4 R17.1 R18.1 R19.1 R23.2
GND: C29.1 C30.1 D1.2(K) D2.2(K) D3.2(K) N4.18(GND) P6.6 P7.3 P7.4
SPI1_CS_SRAM1: N4.26(PB8) ; port SRAM1_CS
SPI1_CS_SRAM2: N4.25(PB9) ; port SRAM2_CS
SPI1_CS_SRAM3: N4.24(PB10) ; port SRAM3_CS
SPI1_MISO: N4.8(PA6_AIN6) ; port SPI1_MISO
SPI1_MOSI: N4.22(PA5) ; port SPI1_MOSI
SPI1_SCK: N4.7(PA7_AIN5) ; port SPI1_SCK
SPI2_MISO: P6.7 P7.9 R17.2 ; port SPI2_MISO  [project net SPI1_SRAM_MISO]
SPI2_MOSI: P6.3 P7.7 R18.2 ; port SPI2_MOSI  [project net SPI1_SRAM_MOSI]
SPI2_NSS: P6.2 P7.11 R19.2 ; port SPI2_NSS
SPI2_SCK: P6.5 P7.5 ; port SPI2_SCK  [project net SPI1_SRAM_SCK]
NetD1_1: D1.1(A) R16.2
NetD2_1: D2.1(A) R20.2
NetD3_1: D3.1(A) R21.2
NetN3_11: N4.6(PA4_AIN4) ; port SPI1_NSS
NetN3_14: N4.28(PC12) ; port ADC_NALARM
NetN4_1: N4.1(PB4_AREF) ; port DAC_NRESET
NetN4_2: N4.2(PA0_AIN0) ; port ADC
NetN4_3: N4.3(PA1_AIN1) ; port DAC_CS
NetN4_4: N4.4(PA2_AIN2) ; port DAC_GAIN
NetN4_9: N4.9(PC0) ; port cal_Select_Reset
NetN4_10: N4.10(PC1) ; port cal_Select_set
NetN4_11: N4.11(PC2) ; port Range_Select_Reset
NetN4_12: N4.12(PC3) ; port Range_Select_set
NetN4_13: N4.13(PB7) ; port OPV_PSU_EN
NetN4_17: N4.17(33V_OUT) R16.1
NetN4_20: N4.20(PB1) ; port ANALOG_5V_PSU_EN
NetN4_21: N4.21(PB0) ; port OW_BUS_MASTER
NetN4_27: N4.27(PC13) ; port ADC_NRESET
NetP6_1: P6.1 P6.8 R23.1
NetP7_6: P7.6 R21.1
NetP7_8: P7.8 R20.1
NetP7_10: P7.10 ; port SD_PSU_EN
NetP7_12: P7.12 ; port PER_33V_PSU_EN

Not connected (* = marked no-connect by the designer): N4 5(PA3_AIN3) 14(PB6) 15(5V_OUT) 16(5V_IN) 19(RESET) 23(PB11)

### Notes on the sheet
- DAT2
- CD/DAT3
- CMD
- VDD
- CLK
- VSS
- DAT0
- DAT1
- PC6
- PB12
- PC10
- PA11
- PA12
- PB15
- PB14
- PB13
- GREEN LED for System status is in Order.
  RED LED for System has fatal error.
  GREEN blinking is for initaliesierung

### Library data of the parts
C29 C30 = Capacitor: as C55 on sheet Top_Sheet
D1-D3 = LED0: Typical INFRARED GaAs LED
P6 = 472192001: 1.10mm Pitch microSD Card Connector, Hinge Type, Lead-Free; Manufacturer_Name: Molex Connector Corporation
P7 = Header 6X2: Header, 6-Pin, Dual row
R16-R21 R23 = ResistorSMD: as R2 on sheet Source_TIA

## Sheet Cal.SchDoc: Relai MOSFET Controller
size A4; DrawnBy: Michael Watzek; Organization: HTL Hollabrunn; Address1: Abteilung Elektronik; Address2: Anton Ehrenfried-Straße 10; Address3: 2020 Hollabrunn; DocumentNumber: 12; Revision: 01; SheetNumber: 12; SheetTotal: 12
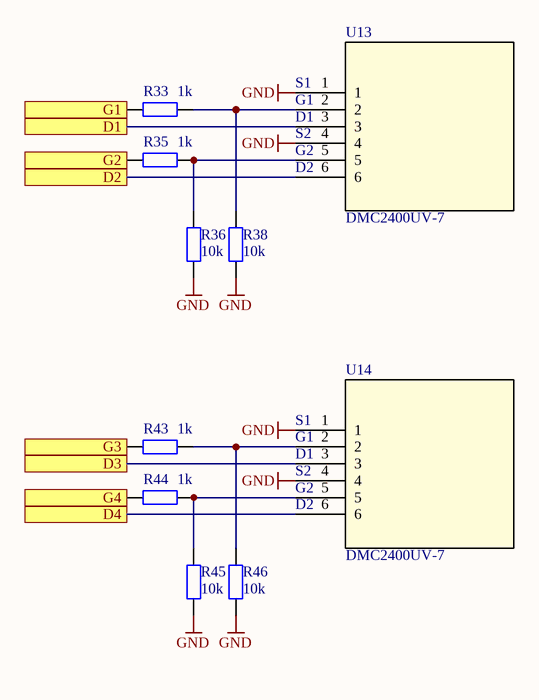
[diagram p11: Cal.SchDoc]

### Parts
R33  1k  [C1206-KUE]
R35  1k  [C1206-KUE]
R36  10k  [C1206-KUE]
R38  10k  [C1206-KUE]
R43  1k  [C1206-KUE]
R44  1k  [C1206-KUE]
R45  10k  [C1206-KUE]
R46  10k  [C1206-KUE]
U13  DMC2400UV-7  [SON_400UV-7_DIO]
U14  DMC2400UV-7  [SON_400UV-7_DIO]

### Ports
D1, D2, D3, D4, G1, G2, G3, G4

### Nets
GND: R36.2 R38.2 R45.2 R46.2 U13.1 U13.4 U14.1 U14.4
NetD5_2: U13.6 ; port D2
NetD6_2: U13.3 ; port D1
NetD7_2: U14.3 ; port D3
NetD8_2: U14.6 ; port D4
NetN4_9: R44.2 ; port G4
NetN4_10: R43.2 ; port G3
NetN4_11: R33.2 ; port G1
NetN4_12: R35.2 ; port G2
NetR33_1: R33.1 R38.1 U13.2
NetR35_1: R35.1 R36.1 U13.5
NetR43_1: R43.1 R46.1 U14.2
NetR44_1: R44.1 R45.1 U14.5

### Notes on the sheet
- (near U13) S1
- (near U13) G1
- (near U13) D1
- (near U13) S2
- (near U13) G2
- (near U13) D2
- (near U14) S1
- (near U14) G1
- (near U14) D1
- (near U14) S2
- (near U14) G2
- (near U14) D2

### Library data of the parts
R33 R35 R36 R38 R43-R46 = ResistorSMD: as R2 on sheet Source_TIA
U13 U14 = DMC2400UV-7: Description; Manufacturer_Name: Diodes Inc

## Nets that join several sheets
AVDD: ADC_8681 (C13.2 C51.2 N3.2), AD_5689_DAC (C15.2 C16.2 U3.5), Analog_PSU_5 (C27.2 C54.2 U10.9 U10.10)
DVDD: Source_TIA (8 pins), PSRAM_SPI (18 pins), ADC_8681 (5 pins), AD_5689_DAC (C18.2 R12.1 R13.1 U3.11), Temp_Sensors (C53.2 R39.1 R47.1 U9.3), Digital_Psu (C31.2 C32.2 U11.1 U11.2), CortexM3_dev (P7.1 P7.2)
DVDD_SD: Digital_Psu (C34.2 C35.2 U12.1 U12.2), CortexM3_dev (7 pins)
GND: Top_Sheet (10 pins), Source_TIA (9 pins), PSRAM_SPI (9 pins), DAC_Buffer_Filter (10 pins), ADC_8681 (11 pins), AD_5689_DAC (7 pins), Temp_Sensors (C53.1 U9.1 U16.3), Digital_Psu (12 pins), Analog_PSU_5 (8 pins), OPV_psu (16 pins), CortexM3_dev (9 pins), Cal (8 pins)
neg_out: Source_TIA (5 pins), DAC_Buffer_Filter (6 pins), OPV_psu (5 pins)
pos_out: Source_TIA (5 pins), DAC_Buffer_Filter (6 pins), OPV_psu (C6.2 C48.2 U1.9 U1.10)
M_source: Top_Sheet (P1.1), Source_TIA (6 pins)
NetC33_2: Top_Sheet (P8.2), Digital_Psu (C33.2 U11.8)
NetC36_2: Top_Sheet (P12.2), Digital_Psu (C36.2 U12.8)
NetC47_2: Top_Sheet (P4.2), OPV_psu (C47.2 U1.1 U1.2)
NetC49_2: Top_Sheet (P4.4), OPV_psu (5 pins)
NetC55_2: Top_Sheet (C55.2 P5.2), Analog_PSU_5 (U10.1 U10.2)
NetD5_2: Source_TIA (D5.2 K1.7), Cal (U13.6)
NetD6_2: Source_TIA (D6.2 K1.12), Cal (U13.3)
NetD7_2: Source_TIA (D7.2 K2.7), Cal (U14.3)
NetD8_2: Source_TIA (D8.2 K2.12), Cal (U14.6)
NetN3_7: Source_TIA (R4.1), ADC_8681 (N3.7)
NetN3_11: ADC_8681 (N3.11 R11.2), CortexM3_dev (N4.6)
NetN3_14: ADC_8681 (N3.14), CortexM3_dev (N4.28)
NetN4_1: AD_5689_DAC (R12.2 U3.15), CortexM3_dev (N4.1)
NetN4_2: Top_Sheet (P9.1), CortexM3_dev (N4.2)
NetN4_3: AD_5689_DAC (R13.2 U3.13), CortexM3_dev (N4.3)
NetN4_4: AD_5689_DAC (U3.10), CortexM3_dev (N4.4)
NetN4_9: CortexM3_dev (N4.9), Cal (R44.2)
NetN4_10: CortexM3_dev (N4.10), Cal (R43.2)
NetN4_11: CortexM3_dev (N4.11), Cal (R33.2)
NetN4_12: CortexM3_dev (N4.12), Cal (R35.2)
NetN4_13: OPV_psu (U1.3 U2.3), CortexM3_dev (N4.13)
NetN4_20: Analog_PSU_5 (U10.3), CortexM3_dev (N4.20)
NetN4_21: Temp_Sensors (P10.1 P11.1), CortexM3_dev (N4.21)
NetN4_27: ADC_8681 (R10.1), CortexM3_dev (N4.27)
NetP2_1: Top_Sheet (P2.1), DAC_Buffer_Filter (U7.1 U7.4)
NetP3_1: Top_Sheet (P3.1), DAC_Buffer_Filter (U8.1 U8.4)
NetP7_10: Digital_Psu (U11.5), CortexM3_dev (P7.10)
NetP7_12: Digital_Psu (U12.5), CortexM3_dev (P7.12)
NetR34_1: DAC_Buffer_Filter (R34.1), AD_5689_DAC (U3.3)
NetR37_1: DAC_Buffer_Filter (R37.1), AD_5689_DAC (U3.7)
SPI1_CS_SRAM1: PSRAM_SPI (R24.2 U4.1), CortexM3_dev (N4.26)
SPI1_CS_SRAM2: PSRAM_SPI (R27.2 U5.1), CortexM3_dev (N4.25)
SPI1_CS_SRAM3: PSRAM_SPI (R30.2 U6.1), CortexM3_dev (N4.24)
SPI1_MISO: ADC_8681 (N3.13), AD_5689_DAC (U3.8), CortexM3_dev (N4.8)
SPI1_MOSI: ADC_8681 (N3.10), AD_5689_DAC (U3.14), CortexM3_dev (N4.22)
SPI1_SCK: ADC_8681 (N3.12), AD_5689_DAC (U3.12), CortexM3_dev (N4.7)
SPI1_SRAM_MISO: PSRAM_SPI (U4.2 U5.2 U6.2), CortexM3_dev (P6.7 P7.9 R17.2)
SPI1_SRAM_MOSI: PSRAM_SPI (U4.5 U5.5 U6.5), CortexM3_dev (P6.3 P7.7 R18.2)
SPI1_SRAM_SCK: PSRAM_SPI (U4.6 U5.6 U6.6), CortexM3_dev (P6.5 P7.5)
